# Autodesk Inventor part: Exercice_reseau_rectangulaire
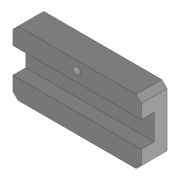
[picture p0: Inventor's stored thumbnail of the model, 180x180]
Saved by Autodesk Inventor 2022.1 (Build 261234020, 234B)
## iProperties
Created: 2014-06
Part Number: Exercice_reseau_rectangulaire
Material: Générique
Document SubType Name: Modeling
Designer: Fabian
Density: 1 g/cm^3
Appearance: Gris clair
Mass: 9.63726 g
Surface Area: 46.5758 cm^2
Volume: 9.63726 cm^3
Author: Fabian
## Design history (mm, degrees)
sketch "Esquisse1"
  geometry: L1 (-23, 12.5)-(23, 12.5); L2 (25, 10.5)-(25, -10.5); L3 (23, -12.5)-(-23, -12.5); L4 (-25, -10.5)-(-25, 10.5); L5 (0, 12.5)-(0, -12.5); L6 (-25, 10.5)-(-23, 12.5); L7 (-25, -10.5)-(-23, -12.5); L8 (25, -10.5)-(23, -12.5); L9 (23, 12.5)-(25, 10.5); L10 (-25, 0)-(25, 0); L11 (-25, 5)-(25, 5); L12 (-25, -5)-(25, -5); 6 further points
  constraints: 24 end point, 12 point on line, 5 midpoint, 2 parallel, 2 perpendicular, 1 coincident, 1 horizontal
  dimensions: "d0" = 50 distance of point (-25, 12.5) point (25, 12.5); "d1" = 25 distance of point (-25, -12.5) point (-25, 12.5) (= 0.5 x d0); "d2" = 2 distance of L4.end point (-25, 12.5); "d3" = 2 distance of L1.start point (-25, 12.5) (= d2); "d4" = 2 distance of L4.start point (-25, -12.5) (= d2); "d5" = 2 distance of L3.end point (-25, -12.5) (= d4); "d6" = 2 distance of L2.end point (25, -12.5) (= d2); "d7" = 2 distance of L3.start point (25, -12.5) (= d6); "d8" = 2 distance of L1.end point (25, 12.5) (= d2); "d9" = 2 distance of L2.start point (25, 12.5) (= d8); "d14" = 10 distance between parallel lines of L12 L11; "d15" = 7.5 distance between parallel lines of L3 L12
extrude "Extrusion1" new body sketch "Esquisse1" distance "d16" = 5; taper "d17" = 0 deg
extrude "Extrusion2" join sketch "Esquisse1" distance "d18" = 5; taper "d19" = 0 deg
sketch "Esquisse2"
  geometry: L1 (23, 12.5)-(-23, 12.5) reference; L2 (25, 5)-(25, 10.5) reference; 2 further points
  dimensions: "d20" = 3.75 distance from line of L1 point (0, 8.75) (= 0.5 x d15); "d21" = 25 distance from line of L2 point (0, 8.75) (= 0.5 x d0)
hole "Perçage1" sketch "Esquisse2" at (0, 8.75) diameter "d22" = 3; stored, may be unused: countersink angle "d26" = 82 deg, drill point angle "d28" = 118 deg; dims "d23" = 6, "d24" = 3.023, "d25" = 2, "d27" = 8
node "Solide1"
